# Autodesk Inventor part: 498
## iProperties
Author: Administrator
Shininess: 64.0
Angle Display Precision: 2
Document Length Units: 11272
Document Angle Units: 11286
Document Time Units: 11279
Document Mass Units: 11290
Document Length Units Precision: 3
Document Angle Units Precision: 2
Compacted: True
PropertySet Name: _Private Model Information
Created: 2002-03
Part Number: 498
Material: Stainless Steel, 440C
Document SubType Name: Modeling
Designer: Administrator
Control State: 0
Master: False
Checked Out: False
PropertySet Name: Design Tracking Control
Density: 0.0
Volumn: 0.0
Area: 0.0
PropertySet Name: Model Information
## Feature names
1. Revolution1
